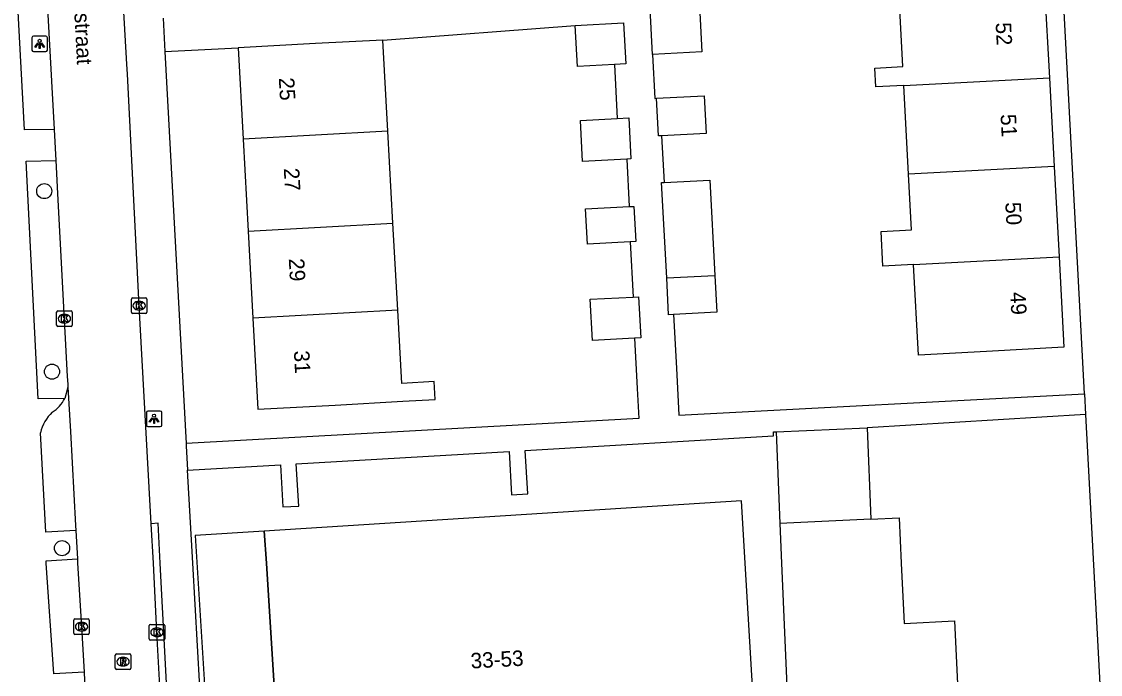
# Model space of a CAD drawing. Extents: x 158087 to 159494, y 382905 to 383981.
# Drawn here: x 158597.5 to 158667.2, y 383492.8 to 383535 of the extents above; entities that cross this region are included whole.
import ezdxf

# ---------------------------------------------------------------- set-up
doc = ezdxf.new("R2010")
doc.units = 0
for name, color, linetype in [('IMGEO_Boom', 7, 'Continuous'), ('IMGEO_Kolk', 7, 'Continuous'), ('IMGEO_Lichtpunt', 7, 'Continuous'), ('IMGEO_Openbare_ruimte_label', 7, 'Continuous'), ('IMGEO_Pand', 7, 'Continuous'), ('IMGEO_Pand_nummerreeks', 7, 'Continuous'), ('IMGEO_Pand_overbouw', 7, 'Continuous'), ('IMGEO_Parkeervlak_open', 7, 'Continuous'), ('IMGEO_Rijbaan_lokaal_open', 7, 'Continuous'), ('IMGEO_Rioolput', 7, 'Continuous'), ('IMGEO_Voetpad_open', 7, 'Continuous')]:
    doc.layers.add(name, color=color, linetype=linetype)

msp = doc.modelspace()

# ---------------------------------------------------------------- linework, layer by layer
at = {"layer": 'IMGEO_Boom'}
for centre in [(158598.959, 383524.012), (158599.46, 383512.357), (158600.111, 383500.968)]:
    msp.add_circle(centre, 0.489, dxfattribs=at)
at = {"layer": 'IMGEO_Kolk'}
for p, q in [((158604.589, 383516.187), (158604.589, 383517.039)), ((158604.664, 383517.113), (158605.516, 383517.113)), ((158605.59, 383517.039), (158605.59, 383516.187)), ((158599.836, 383516.277), (158600.688, 383516.277)), ((158605.1, 383516.333), (158605.075, 383516.333)), ((158605.077, 383516.893), (158605.102, 383516.893)), ((158599.761, 383515.351), (158599.761, 383516.203)), ((158600.249, 383516.057), (158600.274, 383516.057)), ((158600.762, 383516.203), (158600.762, 383515.351)), ((158605.516, 383516.113), (158604.664, 383516.113)), ((158600.688, 383515.277), (158599.836, 383515.277)), ((158600.272, 383515.497), (158600.247, 383515.497)), ((158600.87, 383495.47), (158600.87, 383496.322)), ((158600.945, 383496.396), (158601.797, 383496.396)), ((158601.358, 383496.176), (158601.383, 383496.176)), ((158601.871, 383496.322), (158601.871, 383495.47)), ((158605.816, 383496.035), (158606.668, 383496.035)), ((158601.797, 383495.396), (158600.945, 383495.396)), ((158601.381, 383495.616), (158601.356, 383495.616)), ((158605.741, 383495.109), (158605.741, 383495.961)), ((158606.229, 383495.815), (158606.254, 383495.815)), ((158606.742, 383495.961), (158606.742, 383495.109)), ((158606.668, 383495.035), (158605.816, 383495.035)), ((158606.252, 383495.255), (158606.227, 383495.255))]:
    msp.add_line(p, q, dxfattribs=at)
for points in [[(158604.589, 383516.187), (158604.589, 383517.039)], [(158604.664, 383517.113), (158605.516, 383517.113)], [(158605.59, 383517.039), (158605.59, 383516.187)], [(158599.836, 383516.277), (158600.688, 383516.277)], [(158604.91, 383516.813), (158605.033, 383516.813), (158605.033, 383516.662), (158605.163, 383516.813), (158605.327, 383516.813), (158605.181, 383516.662), (158605.334, 383516.413), (158605.182, 383516.413), (158605.097, 383516.577), (158605.033, 383516.51), (158605.033, 383516.413), (158604.91, 383516.413), (158604.91, 383516.813)], [(158599.761, 383515.351), (158599.761, 383516.203)], [(158600.082, 383515.977), (158600.205, 383515.977), (158600.205, 383515.826), (158600.335, 383515.977), (158600.499, 383515.977), (158600.353, 383515.826), (158600.506, 383515.577), (158600.354, 383515.577), (158600.269, 383515.741), (158600.205, 383515.674), (158600.205, 383515.577), (158600.082, 383515.577), (158600.082, 383515.977)], [(158600.762, 383516.203), (158600.762, 383515.351)], [(158605.516, 383516.113), (158604.664, 383516.113)], [(158600.688, 383515.277), (158599.836, 383515.277)], [(158600.87, 383495.47), (158600.87, 383496.322)], [(158600.945, 383496.396), (158601.797, 383496.396)], [(158601.191, 383496.096), (158601.314, 383496.096), (158601.314, 383495.945), (158601.444, 383496.096), (158601.608, 383496.096), (158601.462, 383495.945), (158601.615, 383495.696), (158601.463, 383495.696), (158601.378, 383495.86), (158601.314, 383495.793), (158601.314, 383495.696), (158601.191, 383495.696), (158601.191, 383496.096)], [(158601.871, 383496.322), (158601.871, 383495.47)], [(158605.816, 383496.035), (158606.668, 383496.035)], [(158601.797, 383495.396), (158600.945, 383495.396)], [(158605.741, 383495.109), (158605.741, 383495.961)], [(158606.062, 383495.735), (158606.185, 383495.735), (158606.185, 383495.584), (158606.315, 383495.735), (158606.479, 383495.735), (158606.333, 383495.584), (158606.486, 383495.335), (158606.334, 383495.335), (158606.249, 383495.499), (158606.185, 383495.432), (158606.185, 383495.335), (158606.062, 383495.335), (158606.062, 383495.735)], [(158606.742, 383495.961), (158606.742, 383495.109)], [(158606.668, 383495.035), (158605.816, 383495.035)]]:
    msp.add_lwpolyline(points, dxfattribs=at)
for centre, start, end in [((158604.666, 383517.037), 91.55205, 178.44795), ((158604.666, 383517.037), 91.55205, 178.44795), ((158605.514, 383517.037), 1.55205, 88.44795), ((158605.514, 383517.037), 1.55205, 88.44795), ((158599.838, 383516.201), 91.55205, 178.44795), ((158599.838, 383516.201), 91.55205, 178.44795), ((158600.686, 383516.201), 1.55205, 88.44795), ((158600.686, 383516.201), 1.55205, 88.44795), ((158604.666, 383516.189), 181.55205, 268.44795), ((158604.666, 383516.189), 181.55205, 268.44795), ((158605.514, 383516.189), 271.55205, 358.44795), ((158605.514, 383516.189), 271.55205, 358.44795), ((158599.838, 383515.353), 181.55205, 268.44795), ((158599.838, 383515.353), 181.55205, 268.44795), ((158600.686, 383515.353), 271.55205, 358.44795), ((158600.686, 383515.353), 271.55205, 358.44795), ((158600.947, 383496.32), 91.55205, 178.44795), ((158600.947, 383496.32), 91.55205, 178.44795), ((158601.795, 383496.32), 1.55205, 88.44795), ((158601.795, 383496.32), 1.55205, 88.44795), ((158605.818, 383495.959), 91.55205, 178.44795), ((158605.818, 383495.959), 91.55205, 178.44795), ((158606.666, 383495.959), 1.55205, 88.44795), ((158606.666, 383495.959), 1.55205, 88.44795), ((158600.947, 383495.472), 181.55205, 268.44795), ((158600.947, 383495.472), 181.55205, 268.44795), ((158601.795, 383495.472), 271.55205, 358.44795), ((158601.795, 383495.472), 271.55205, 358.44795), ((158605.818, 383495.111), 181.55205, 268.44795), ((158605.818, 383495.111), 181.55205, 268.44795), ((158606.666, 383495.111), 271.55205, 358.44795), ((158606.666, 383495.111), 271.55205, 358.44795)]:
    msp.add_arc(centre, 0.0765, start, end, dxfattribs=at)
for centre, major_axis, ratio, start_param, end_param in [((158605.076, 383516.613), (-0.387, 0.002), 0.722429, 4.712389, 7.853982), ((158605.101, 383516.613), (-0.39, 0.002), 0.717154, 1.570796, 4.712389), ((158600.248, 383515.777), (-0.387, 0.002), 0.722429, 4.712389, 7.853982), ((158600.273, 383515.777), (-0.39, 0.002), 0.717154, 1.570796, 4.712389), ((158601.357, 383495.896), (-0.387, 0.002), 0.722429, 4.712389, 7.853982), ((158601.382, 383495.896), (-0.39, 0.002), 0.717154, 1.570796, 4.712389), ((158606.228, 383495.535), (-0.387, 0.002), 0.722429, 4.712389, 7.853982), ((158606.253, 383495.535), (-0.39, 0.002), 0.717154, 1.570796, 4.712389)]:
    msp.add_ellipse(centre, major_axis=major_axis, ratio=ratio, start_param=start_param, end_param=end_param, dxfattribs=at)
at = {"layer": 'IMGEO_Lichtpunt'}
for p, q in [((158598.163, 383533.914), (158598.163, 383533.107)), ((158598.163, 383533.914), (158598.163, 383533.107)), ((158599.065, 383534.009), (158598.257, 383534.009)), ((158599.065, 383534.009), (158598.257, 383534.009)), ((158599.159, 383533.107), (158599.159, 383533.914)), ((158599.159, 383533.107), (158599.159, 383533.914)), ((158598.257, 383533.013), (158599.065, 383533.013)), ((158598.257, 383533.013), (158599.065, 383533.013)), ((158605.555, 383509.714), (158605.555, 383508.907)), ((158605.555, 383509.714), (158605.555, 383508.907)), ((158606.457, 383509.809), (158605.649, 383509.809)), ((158606.457, 383509.809), (158605.649, 383509.809)), ((158606.551, 383508.907), (158606.551, 383509.714)), ((158606.551, 383508.907), (158606.551, 383509.714)), ((158605.649, 383508.813), (158606.457, 383508.813)), ((158605.649, 383508.813), (158606.457, 383508.813))]:
    msp.add_line(p, q, dxfattribs=at)
for points in [[(158598.537, 383533.578), (158598.576, 383533.55), (158598.388, 383533.288), (158598.35, 383533.315), (158598.537, 383533.578)], [(158598.639, 383533.53), (158598.686, 383533.53), (158598.686, 383533.208), (158598.639, 383533.208), (158598.639, 383533.53)], [(158598.749, 383533.55), (158598.787, 383533.577), (158598.974, 383533.315), (158598.935, 383533.287), (158598.749, 383533.55)], [(158605.929, 383509.378), (158605.968, 383509.35), (158605.78, 383509.088), (158605.742, 383509.115), (158605.929, 383509.378)], [(158606.031, 383509.33), (158606.078, 383509.33), (158606.078, 383509.008), (158606.031, 383509.008), (158606.031, 383509.33)], [(158606.141, 383509.35), (158606.179, 383509.377), (158606.366, 383509.115), (158606.327, 383509.087), (158606.141, 383509.35)]]:
    msp.add_lwpolyline(points, dxfattribs=at)
for centre in [(158598.662, 383533.712), (158606.054, 383509.512)]:
    msp.add_circle(centre, 0.0994, dxfattribs=at)
for centre, start, end in [((158598.257, 383533.914), 90, 180), ((158598.257, 383533.914), 90, 180), ((158599.065, 383533.914), 0, 90), ((158599.065, 383533.914), 0, 90), ((158598.257, 383533.107), 180, 270), ((158598.257, 383533.107), 180, 270), ((158599.065, 383533.107), 270, 0), ((158599.065, 383533.107), 270, 360), ((158605.649, 383509.714), 90, 180), ((158605.649, 383509.714), 90, 180), ((158606.457, 383509.714), 0, 90), ((158606.457, 383509.714), 0, 90), ((158605.649, 383508.907), 180, 270), ((158605.649, 383508.907), 180, 270), ((158606.457, 383508.907), 270, 0), ((158606.457, 383508.907), 270, 360)]:
    msp.add_arc(centre, 0.0946, start, end, dxfattribs=at)
at = {"layer": 'IMGEO_Pand'}
for points in [[(158654.483, 383530.818), (158652.664, 383530.751), (158652.599, 383531.948), (158654.417, 383532.046), (158654.173, 383536.564)], [(158663.574, 383537.071), (158663.884, 383531.325)], [(158638.245, 383532.835), (158638.089, 383535.771), (158638.365, 383535.786)], [(158638.365, 383535.786), (158641.279, 383535.94), (158641.435, 383533.004), (158638.245, 383532.835)], [(158633.261, 383534.705), (158636.384, 383534.868), (158636.522, 383532.217), (158635.785, 383532.179)], [(158635.785, 383532.179), (158633.399, 383532.054), (158633.261, 383534.705)], [(158620.835, 383533.751), (158616.47, 383533.544), (158611.477, 383533.269)], [(158621.157, 383527.872), (158620.835, 383533.751)], [(158611.477, 383533.269), (158611.803, 383527.356)], [(158654.483, 383530.818), (158663.884, 383531.325)], [(158663.884, 383531.325), (158664.192, 383525.603)], [(158638.5, 383530.004), (158641.591, 383530.168), (158641.72, 383527.732), (158638.834, 383527.579)], [(158654.792, 383525.096), (158654.483, 383530.818)], [(158638.834, 383527.579), (158638.629, 383527.568), (158638.5, 383530.004)], [(158636.584, 383526.077), (158633.733, 383525.928), (158633.595, 383528.579), (158635.967, 383528.703)], [(158635.967, 383528.703), (158636.719, 383528.742), (158636.857, 383526.091), (158636.584, 383526.077)], [(158621.157, 383527.872), (158611.803, 383527.356)], [(158621.481, 383521.942), (158621.157, 383527.872)], [(158611.803, 383527.356), (158612.13, 383521.426)], [(158664.192, 383525.603), (158654.792, 383525.096)], [(158664.192, 383525.603), (158664.507, 383519.771)], [(158638.993, 383524.566), (158641.954, 383524.723), (158642.28, 383518.572)], [(158655.106, 383519.264), (158653.131, 383519.157), (158653.01, 383521.399), (158654.985, 383521.505), (158654.792, 383525.096)], [(158639.165, 383518.404), (158638.839, 383524.558), (158638.993, 383524.566)], [(158636.804, 383520.734), (158634.041, 383520.59), (158633.922, 383522.865), (158636.745, 383523.012)], [(158636.745, 383523.012), (158637.045, 383523.028), (158637.164, 383520.753), (158636.804, 383520.734)], [(158612.13, 383521.426), (158621.481, 383521.942)], [(158621.788, 383516.331), (158621.481, 383521.942)], [(158612.13, 383521.426), (158612.439, 383515.815)], [(158664.507, 383519.771), (158664.822, 383513.933), (158659.83, 383513.664), (158655.421, 383513.426), (158655.106, 383519.264)], [(158655.106, 383519.264), (158664.507, 383519.771)], [(158639.165, 383518.404), (158642.28, 383518.572)], [(158639.612, 383516.041), (158639.291, 383516.024), (158639.165, 383518.404)], [(158642.28, 383518.572), (158642.406, 383516.189), (158639.612, 383516.041)], [(158637.092, 383514.52), (158634.365, 383514.378), (158634.227, 383517.029), (158636.99, 383517.173)], [(158636.99, 383517.173), (158637.35, 383517.192), (158637.488, 383514.541), (158637.092, 383514.52)], [(158621.788, 383516.331), (158612.439, 383515.815)], [(158612.439, 383515.815), (158612.764, 383509.928), (158617.757, 383510.204), (158622.111, 383510.444), (158624.212, 383510.56), (158624.148, 383511.716), (158622.047, 383511.601), (158621.788, 383516.331)], [(158646.227, 383508.481), (158652.105, 383508.733)], [(158652.105, 383508.733), (158652.357, 383502.827)], [(158646.227, 383508.481), (158646.481, 383502.547)], [(158643.439, 383491.582), (158644.734, 383491.659), (158644.238, 383500), (158644, 383504.009), (158613.175, 383502.059), (158613.305, 383500), (158613.939, 383489.984), (158629.826, 383490.845), (158631.02, 383490.909), (158642.554, 383491.534)], [(158646.481, 383502.547), (158646.59, 383500), (158647.886, 383469.682), (158637.621, 383469.091)], [(158652.357, 383502.827), (158654.173, 383502.913), (158654.312, 383500), (158654.497, 383496.111), (158657.764, 383496.267), (158658.774, 383475.051), (158655.697, 383474.905), (158655.929, 383470.015), (158656.879, 383470.06), (158656.922, 383469.151), (158656.222, 383469.118), (158656.232, 383468.894), (158656.07, 383468.886), (158656.747, 383454.587), (158638.28, 383456.476)], [(158652.357, 383502.827), (158646.481, 383502.547)]]:
    msp.add_lwpolyline(points, dxfattribs=at)
at = {"layer": 'IMGEO_Pand_overbouw'}
msp.add_lwpolyline([(158613.939, 383489.984), (158613.305, 383500), (158613.175, 383502.059), (158608.702, 383501.776), (158609.464, 383489.741)], close=True, dxfattribs=at)
at = {"layer": 'IMGEO_Parkeervlak_open'}
msp.add_lwpolyline([(158600.484, 383511.348), (158600.283, 383510.625)], dxfattribs=at)
at = {"layer": 'IMGEO_Rijbaan_lokaal_open'}
for points in [[(158605.871, 383502.536), (158605.085, 383516.613), (158604.332, 383531.556), (158604.294, 383532.21), (158604.075, 383535.954), (158603.307, 383549.063), (158602.483, 383563.627), (158601.748, 383577.901), (158601.347, 383584.473)], [(158598.768, 383543.224), (158599.598, 383527.989)], [(158599.598, 383527.989), (158599.708, 383525.983)], [(158599.708, 383525.983), (158599.824, 383523.85), (158600.444, 383512.041), (158600.493, 383511.554), (158600.484, 383511.348)], [(158600.484, 383511.348), (158600.649, 383508.494), (158600.984, 383502.435), (158601.001, 383502.108)], [(158606.615, 383488.563), (158606.241, 383495.536), (158606.013, 383500), (158605.871, 383502.536)], [(158601.001, 383502.108), (158601.099, 383500.269)], [(158601.099, 383500.269), (158601.116, 383500), (158601.372, 383495.896), (158601.528, 383492.961)], [(158601.528, 383492.961), (158601.673, 383489.743)]]:
    msp.add_lwpolyline(points, dxfattribs=at)
at = {"layer": 'IMGEO_Rioolput'}
for p, q in [((158603.55, 383493.212), (158603.55, 383494.064)), ((158603.625, 383494.138), (158604.477, 383494.138)), ((158604.551, 383494.064), (158604.551, 383493.212)), ((158604.061, 383493.358), (158604.036, 383493.358)), ((158604.038, 383493.918), (158604.063, 383493.918)), ((158604.477, 383493.138), (158603.625, 383493.138))]:
    msp.add_line(p, q, dxfattribs=at)
for points in [[(158603.55, 383493.212), (158603.55, 383494.064)], [(158603.625, 383494.138), (158604.477, 383494.138)], [(158604.551, 383494.064), (158604.551, 383493.212)], [(158604.139, 383493.836), (158603.887, 383493.838), (158603.887, 383493.438)], [(158603.887, 383493.438), (158604.011, 383493.438), (158604.011, 383493.6), (158604.022, 383493.6)], [(158604.065, 383493.757), (158604.011, 383493.757), (158604.011, 383493.676)], [(158604.011, 383493.676), (158604.063, 383493.676)], [(158604.069, 383493.571), (158604.14, 383493.438), (158604.28, 383493.438), (158604.215, 383493.564)], [(158604.477, 383493.138), (158603.625, 383493.138)]]:
    msp.add_lwpolyline(points, dxfattribs=at)
for centre, radius, start, end in [((158603.627, 383494.062), 0.0765, 91.55205, 178.44795), ((158603.627, 383494.062), 0.0765, 91.55205, 178.44795), ((158604.475, 383494.062), 0.0765, 1.55205, 88.44795), ((158604.475, 383494.062), 0.0765, 1.55205, 88.44795), ((158604.021, 383493.547), 0.0533, 26.02933, 88.69889), ((158604.047, 383493.865), 0.19, 274.7715, 282.96867), ((158604.071, 383493.661), 0.0964, 77.00612, 93.18647), ((158604.085, 383493.718), 0.0378, 276.66336, 79.67722), ((158604.138, 383493.726), 0.109, 350.36119, 89.41601), ((158604.136, 383493.726), 0.112, 277.58423, 350.98172), ((158604.12, 383493.511), 0.108, 29.51342, 73.79051), ((158603.627, 383493.214), 0.0765, 181.55205, 268.44795), ((158603.627, 383493.214), 0.0765, 181.55205, 268.44795), ((158604.475, 383493.214), 0.0765, 271.55205, 358.44795), ((158604.475, 383493.214), 0.0765, 271.55205, 358.44795)]:
    msp.add_arc(centre, radius, start, end, dxfattribs=at)
for centre, major_axis, ratio, start_param, end_param in [((158604.037, 383493.638), (-0.387, 0.002), 0.722429, 4.712389, 7.853982), ((158604.062, 383493.638), (-0.39, 0.002), 0.717154, 1.570796, 4.712389)]:
    msp.add_ellipse(centre, major_axis=major_axis, ratio=ratio, start_param=start_param, end_param=end_param, dxfattribs=at)
at = {"layer": 'IMGEO_Voetpad_open'}
for points in [[(158666.144, 383510.926), (158662.901, 383571.964)], [(158599.598, 383527.989), (158597.691, 383527.956), (158596.86, 383543.191), (158598.768, 383543.224)], [(158606.636, 383535.182), (158606.753, 383533.014)], [(158620.835, 383533.751), (158633.261, 383534.705)], [(158606.753, 383533.014), (158611.477, 383533.269)], [(158606.753, 383533.014), (158608.118, 383507.728)], [(158638.245, 383532.835), (158638.401, 383529.999), (158638.5, 383530.004)], [(158635.785, 383532.179), (158635.967, 383528.703)], [(158638.834, 383527.579), (158638.993, 383524.566)], [(158636.584, 383526.077), (158636.745, 383523.012)], [(158600.283, 383510.625), (158598.559, 383510.597), (158597.8, 383525.95), (158599.708, 383525.983)], [(158636.804, 383520.734), (158636.99, 383517.173)], [(158639.612, 383516.041), (158639.796, 383512.583), (158639.957, 383509.538), (158666.144, 383510.926)], [(158637.092, 383514.52), (158637.262, 383511.279), (158637.368, 383509.34), (158608.118, 383507.728)], [(158666.144, 383510.926), (158666.215, 383509.595)], [(158666.215, 383509.595), (158652.105, 383508.733)], [(158666.215, 383509.595), (158669.483, 383448.061)], [(158601.001, 383502.108), (158599.07, 383502.003), (158598.721, 383508.414)], [(158608.217, 383506.002), (158614.214, 383506.351), (158614.373, 383503.622), (158615.397, 383503.681), (158615.238, 383506.41), (158628.988, 383507.21), (158629.151, 383504.405), (158630.192, 383504.465), (158630.029, 383507.271), (158646.069, 383508.204), (158646.056, 383508.476), (158646.227, 383508.481)], [(158608.118, 383507.728), (158608.127, 383507.568), (158608.217, 383506.002)], [(158609.453, 383483.978), (158608.564, 383500), (158608.217, 383506.002)], [(158606.615, 383488.563), (158607.047, 383488.583), (158606.449, 383500), (158606.314, 383502.571), (158605.871, 383502.536)], [(158601.528, 383492.961), (158599.578, 383492.861), (158599.087, 383500), (158599.077, 383500.138), (158601.099, 383500.269)]]:
    msp.add_lwpolyline(points, dxfattribs=at)
for centre, radius, start, end in [((158598.404, 383511.531), 2.086, 300.81936, 334.24776), ((158601.314, 383507.819), 2.661, 133.79519, 167.088)]:
    msp.add_arc(centre, radius, start, end, dxfattribs=at)

# ---------------------------------------------------------------- texts
at = {"layer": 'IMGEO_Openbare_ruimte_label'}
msp.add_text('Gerard Noodtstraat', height=1, rotation=272.97967, dxfattribs=at).set_placement((158600.482, 383543.589))
at = {"layer": 'IMGEO_Pand_nummerreeks'}
for s, rotation, p in [('52', 273.08803, (158660.408, 383534.873)), ('25', 273.15604, (158614.108, 383531.315)), ('51', 273.0878, (158660.726, 383528.961)), ('27', 273.15679, (158614.43, 383525.48)), ('50', 273.08803, (158661.033, 383523.274)), ('29', 273.15604, (158614.752, 383519.645)), ('49', 273.0878, (158661.346, 383517.48)), ('31', 273.15679, (158615.081, 383513.696)), ('33-53', 3.11336, (158626.528, 383493.192))]:
    msp.add_text(s, height=1, rotation=rotation, dxfattribs=at).set_placement(p)

doc.saveas('drawing.dxf')
